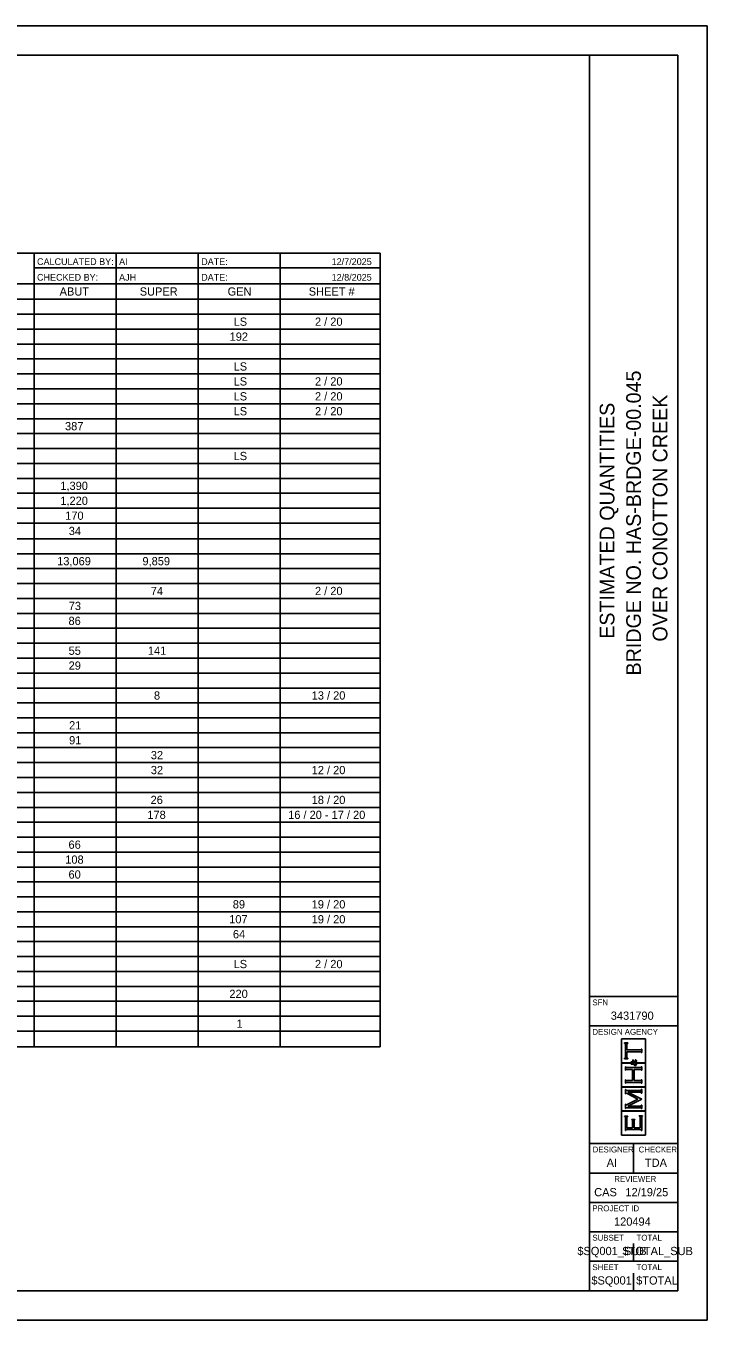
# Model space of a CAD drawing. Extents: x 0 to 34, y 0 to 22.
# Drawn here: x 22.42 to 34, y 0 to 22 of the extents above; entities that cross this region are included whole.
import ezdxf

# ---------------------------------------------------------------- set-up
doc = ezdxf.new("R2010")
doc.units = 0
for name, color, linetype in [('SH_Border', 7, 'Continuous'), ('SH_Cut_Line', 7, 'Continuous'), ('SH_Data', 7, 'Continuous'), ('SH_Text', 7, 'Continuous')]:
    doc.layers.add(name, color=color, linetype=linetype)

msp = doc.modelspace()

# ---------------------------------------------------------------- linework, layer by layer
at = {"layer": 'SH_Border'}
for p, q in [((32, 0.5), (32, 21.5)), ((32, 5.5), (33.5, 5.5)), ((32, 5), (33.5, 5)), ((32, 3), (33.5, 3)), ((32.75, 3), (32.75, 2.5)), ((32, 2.5), (33.5, 2.5)), ((32, 2), (33.5, 2)), ((32, 1.5), (33.5, 1.5)), ((32, 1), (33.5, 1))]:
    msp.add_line(p, q, dxfattribs=at)
msp.add_lwpolyline([(1.5, 21.5), (33.5, 21.5), (33.5, 0.5), (1.5, 0.5)], close=True, dxfattribs=at)
at = {"layer": 'SH_Cut_Line'}
msp.add_lwpolyline([(0, 0), (34, 0), (34, 22), (0, 22)], close=True, dxfattribs=at)
at = {"layer": 'SH_Data'}
for p, q in [((32.952, 4.779), (32.547, 4.779)), ((32.547, 4.779), (32.547, 4.375)), ((32.598, 4.704), (32.598, 4.711)), ((32.598, 4.711), (32.65, 4.711)), ((32.603, 4.703), (32.598, 4.704)), ((32.606, 4.701), (32.603, 4.703)), ((32.608, 4.699), (32.606, 4.701)), ((32.61, 4.696), (32.608, 4.699)), ((32.611, 4.692), (32.61, 4.696)), ((32.611, 4.687), (32.611, 4.692)), ((32.611, 4.468), (32.611, 4.687)), ((32.638, 4.696), (32.637, 4.692)), ((32.637, 4.692), (32.637, 4.687)), ((32.637, 4.687), (32.637, 4.593)), ((32.64, 4.699), (32.638, 4.696)), ((32.642, 4.701), (32.64, 4.699)), ((32.645, 4.703), (32.642, 4.701)), ((32.65, 4.704), (32.645, 4.703)), ((32.65, 4.711), (32.65, 4.704)), ((32.952, 4.375), (32.952, 4.779)), ((32.598, 4.45), (32.603, 4.451)), ((32.598, 4.444), (32.598, 4.45)), ((32.65, 4.444), (32.598, 4.444)), ((32.603, 4.451), (32.606, 4.453)), ((32.606, 4.453), (32.608, 4.455)), ((32.608, 4.455), (32.61, 4.458)), ((32.61, 4.458), (32.611, 4.462)), ((32.611, 4.462), (32.611, 4.468)), ((32.637, 4.593), (32.864, 4.593)), ((32.864, 4.561), (32.637, 4.561)), ((32.637, 4.561), (32.637, 4.468)), ((32.637, 4.468), (32.637, 4.462)), ((32.637, 4.462), (32.638, 4.458)), ((32.638, 4.458), (32.64, 4.455)), ((32.64, 4.455), (32.642, 4.453)), ((32.642, 4.453), (32.645, 4.451)), ((32.645, 4.451), (32.65, 4.45)), ((32.65, 4.45), (32.65, 4.444)), ((32.738, 4.393), (32.738, 4.422)), ((32.738, 4.422), (32.741, 4.422)), ((32.741, 4.422), (32.741, 4.418)), ((32.741, 4.418), (32.742, 4.415)), ((32.742, 4.415), (32.743, 4.413)), ((32.743, 4.413), (32.745, 4.411)), ((32.745, 4.411), (32.749, 4.408)), ((32.749, 4.408), (32.756, 4.404)), ((32.756, 4.404), (32.763, 4.4)), ((32.763, 4.4), (32.77, 4.396)), ((32.779, 4.423), (32.781, 4.426)), ((32.782, 4.422), (32.779, 4.423)), ((32.781, 4.426), (32.787, 4.424)), ((32.785, 4.421), (32.782, 4.422)), ((32.784, 4.398), (32.786, 4.401)), ((32.786, 4.419), (32.785, 4.421)), ((32.788, 4.417), (32.786, 4.419)), ((32.786, 4.401), (32.788, 4.404)), ((32.787, 4.424), (32.792, 4.421)), ((32.789, 4.414), (32.788, 4.417)), ((32.788, 4.404), (32.789, 4.408)), ((32.789, 4.411), (32.789, 4.414)), ((32.789, 4.408), (32.789, 4.411)), ((32.792, 4.421), (32.795, 4.418)), ((32.795, 4.418), (32.798, 4.414)), ((32.798, 4.414), (32.799, 4.41)), ((32.799, 4.401), (32.798, 4.397)), ((32.799, 4.41), (32.799, 4.405)), ((32.799, 4.405), (32.799, 4.401)), ((32.864, 4.593), (32.869, 4.593)), ((32.87, 4.561), (32.864, 4.561)), ((32.869, 4.593), (32.873, 4.594)), ((32.874, 4.56), (32.87, 4.561)), ((32.873, 4.594), (32.876, 4.596)), ((32.876, 4.559), (32.874, 4.56)), ((32.876, 4.596), (32.878, 4.597)), ((32.878, 4.557), (32.876, 4.559)), ((32.878, 4.597), (32.88, 4.601)), ((32.88, 4.553), (32.878, 4.557)), ((32.88, 4.601), (32.881, 4.606)), ((32.881, 4.548), (32.88, 4.553)), ((32.881, 4.606), (32.888, 4.606)), ((32.888, 4.548), (32.881, 4.548)), ((32.888, 4.606), (32.888, 4.548)), ((32.547, 4.375), (32.696, 4.375)), ((32.696, 4.369), (32.547, 4.369)), ((32.547, 4.369), (32.547, 3.965)), ((32.611, 4.249), (32.611, 4.307)), ((32.611, 4.307), (32.617, 4.307)), ((32.617, 4.249), (32.611, 4.249)), ((32.617, 4.307), (32.619, 4.302)), ((32.618, 4.254), (32.617, 4.249)), ((32.62, 4.258), (32.618, 4.254)), ((32.619, 4.302), (32.62, 4.298)), ((32.62, 4.298), (32.623, 4.297)), ((32.623, 4.26), (32.62, 4.258)), ((32.623, 4.297), (32.625, 4.295)), ((32.625, 4.261), (32.623, 4.26)), ((32.625, 4.295), (32.629, 4.294)), ((32.629, 4.262), (32.625, 4.261)), ((32.629, 4.294), (32.635, 4.294)), ((32.635, 4.262), (32.629, 4.262)), ((32.635, 4.294), (32.864, 4.294)), ((32.732, 4.262), (32.635, 4.262)), ((32.696, 4.375), (32.696, 4.369)), ((32.703, 4.379), (32.705, 4.383)), ((32.703, 4.373), (32.703, 4.379)), ((32.703, 4.368), (32.703, 4.373)), ((32.705, 4.363), (32.703, 4.368)), ((32.705, 4.383), (32.708, 4.387)), ((32.708, 4.358), (32.705, 4.363)), ((32.708, 4.387), (32.711, 4.39)), ((32.709, 4.379), (32.708, 4.376)), ((32.708, 4.376), (32.708, 4.373)), ((32.708, 4.373), (32.708, 4.369)), ((32.708, 4.369), (32.71, 4.366)), ((32.712, 4.353), (32.708, 4.358)), ((32.712, 4.381), (32.709, 4.379)), ((32.71, 4.366), (32.712, 4.364)), ((32.711, 4.39), (32.715, 4.392)), ((32.714, 4.383), (32.712, 4.381)), ((32.712, 4.364), (32.715, 4.362)), ((32.718, 4.35), (32.712, 4.353)), ((32.716, 4.384), (32.714, 4.383)), ((32.715, 4.392), (32.72, 4.392)), ((32.715, 4.362), (32.718, 4.361)), ((32.72, 4.384), (32.716, 4.384)), ((32.718, 4.361), (32.721, 4.361)), ((32.726, 4.35), (32.718, 4.35)), ((32.72, 4.392), (32.725, 4.392)), ((32.724, 4.384), (32.72, 4.384)), ((32.721, 4.361), (32.723, 4.361)), ((32.723, 4.361), (32.725, 4.362)), ((32.728, 4.382), (32.724, 4.384)), ((32.725, 4.392), (32.729, 4.39)), ((32.725, 4.362), (32.728, 4.362)), ((32.729, 4.35), (32.726, 4.35)), ((32.731, 4.38), (32.728, 4.382)), ((32.728, 4.362), (32.731, 4.363)), ((32.729, 4.39), (32.732, 4.387)), ((32.731, 4.35), (32.729, 4.35)), ((32.734, 4.377), (32.731, 4.38)), ((32.731, 4.363), (32.735, 4.365)), ((32.734, 4.351), (32.731, 4.35)), ((32.732, 4.387), (32.736, 4.383)), ((32.732, 4.072), (32.732, 4.262)), ((32.737, 4.372), (32.734, 4.377)), ((32.737, 4.352), (32.734, 4.351)), ((32.735, 4.365), (32.74, 4.367)), ((32.736, 4.383), (32.74, 4.378)), ((32.74, 4.367), (32.737, 4.372)), ((32.741, 4.353), (32.737, 4.352)), ((32.741, 4.393), (32.738, 4.393)), ((32.74, 4.378), (32.744, 4.369)), ((32.742, 4.396), (32.741, 4.395)), ((32.741, 4.395), (32.741, 4.393)), ((32.746, 4.355), (32.741, 4.353)), ((32.743, 4.397), (32.742, 4.396)), ((32.745, 4.399), (32.743, 4.397)), ((32.744, 4.369), (32.754, 4.375)), ((32.746, 4.399), (32.745, 4.399)), ((32.748, 4.399), (32.746, 4.399)), ((32.752, 4.344), (32.746, 4.355)), ((32.755, 4.399), (32.748, 4.399)), ((32.756, 4.36), (32.751, 4.357)), ((32.751, 4.357), (32.754, 4.352)), ((32.757, 4.337), (32.752, 4.344)), ((32.754, 4.375), (32.764, 4.381)), ((32.754, 4.352), (32.757, 4.348)), ((32.763, 4.395), (32.755, 4.399)), ((32.761, 4.363), (32.756, 4.36)), ((32.757, 4.348), (32.761, 4.345)), ((32.763, 4.333), (32.757, 4.337)), ((32.864, 4.262), (32.759, 4.262)), ((32.759, 4.262), (32.759, 4.072)), ((32.764, 4.365), (32.761, 4.363)), ((32.761, 4.345), (32.765, 4.343)), ((32.772, 4.387), (32.763, 4.395)), ((32.768, 4.329), (32.763, 4.333)), ((32.764, 4.381), (32.772, 4.387)), ((32.768, 4.367), (32.764, 4.365)), ((32.765, 4.343), (32.769, 4.341)), ((32.774, 4.372), (32.768, 4.367)), ((32.774, 4.327), (32.768, 4.329)), ((32.769, 4.341), (32.773, 4.341)), ((32.77, 4.396), (32.776, 4.391)), ((32.773, 4.341), (32.778, 4.341)), ((32.782, 4.378), (32.774, 4.372)), ((32.779, 4.327), (32.774, 4.327)), ((32.776, 4.391), (32.781, 4.395)), ((32.778, 4.341), (32.782, 4.343)), ((32.785, 4.327), (32.779, 4.327)), ((32.781, 4.395), (32.784, 4.398)), ((32.786, 4.373), (32.782, 4.378)), ((32.782, 4.343), (32.786, 4.346)), ((32.79, 4.329), (32.785, 4.327)), ((32.791, 4.386), (32.786, 4.381)), ((32.786, 4.381), (32.791, 4.376)), ((32.788, 4.369), (32.786, 4.373)), ((32.786, 4.346), (32.789, 4.349)), ((32.79, 4.367), (32.788, 4.369)), ((32.789, 4.349), (32.791, 4.353)), ((32.791, 4.364), (32.79, 4.367)), ((32.793, 4.334), (32.79, 4.329)), ((32.794, 4.39), (32.791, 4.386)), ((32.791, 4.376), (32.795, 4.37)), ((32.791, 4.361), (32.791, 4.364)), ((32.791, 4.359), (32.791, 4.361)), ((32.791, 4.353), (32.791, 4.359)), ((32.797, 4.338), (32.793, 4.334)), ((32.796, 4.394), (32.794, 4.39)), ((32.795, 4.37), (32.797, 4.366)), ((32.798, 4.397), (32.796, 4.394)), ((32.797, 4.366), (32.798, 4.361)), ((32.799, 4.344), (32.797, 4.338)), ((32.798, 4.361), (32.799, 4.357)), ((32.803, 4.369), (32.799, 4.375)), ((32.799, 4.375), (32.952, 4.375)), ((32.799, 4.357), (32.799, 4.352)), ((32.799, 4.352), (32.799, 4.344)), ((32.952, 4.369), (32.803, 4.369)), ((32.864, 4.294), (32.869, 4.294)), ((32.87, 4.262), (32.864, 4.262)), ((32.869, 4.294), (32.873, 4.295)), ((32.874, 4.261), (32.87, 4.262)), ((32.873, 4.295), (32.876, 4.297)), ((32.876, 4.26), (32.874, 4.261)), ((32.876, 4.297), (32.878, 4.298)), ((32.878, 4.258), (32.876, 4.26)), ((32.878, 4.298), (32.88, 4.302)), ((32.88, 4.254), (32.878, 4.258)), ((32.88, 4.302), (32.881, 4.307)), ((32.881, 4.249), (32.88, 4.254)), ((32.881, 4.307), (32.888, 4.307)), ((32.888, 4.249), (32.881, 4.249)), ((32.888, 4.307), (32.888, 4.249)), ((32.952, 3.965), (32.952, 4.369)), ((32.547, 3.965), (32.952, 3.965)), ((32.611, 4.027), (32.611, 4.085)), ((32.611, 4.085), (32.617, 4.085)), ((32.617, 4.027), (32.611, 4.027)), ((32.617, 4.085), (32.619, 4.08)), ((32.618, 4.032), (32.617, 4.027)), ((32.62, 4.036), (32.618, 4.032)), ((32.619, 4.08), (32.62, 4.076)), ((32.62, 4.076), (32.623, 4.074)), ((32.623, 4.037), (32.62, 4.036)), ((32.623, 4.074), (32.625, 4.073)), ((32.625, 4.039), (32.623, 4.037)), ((32.625, 4.073), (32.629, 4.072)), ((32.629, 4.04), (32.625, 4.039)), ((32.629, 4.072), (32.635, 4.072)), ((32.635, 4.04), (32.629, 4.04)), ((32.635, 4.072), (32.732, 4.072)), ((32.864, 4.04), (32.635, 4.04)), ((32.75, 4), (32.75, 4)), ((32.759, 4.072), (32.864, 4.072)), ((32.864, 4.072), (32.87, 4.072)), ((32.87, 4.04), (32.864, 4.04)), ((32.87, 4.072), (32.874, 4.073)), ((32.874, 4.039), (32.87, 4.04)), ((32.874, 4.073), (32.876, 4.074)), ((32.876, 4.038), (32.874, 4.039)), ((32.876, 4.074), (32.878, 4.076)), ((32.878, 4.036), (32.876, 4.038)), ((32.878, 4.076), (32.88, 4.08)), ((32.88, 4.032), (32.878, 4.036)), ((32.88, 4.08), (32.881, 4.085)), ((32.881, 4.027), (32.88, 4.032)), ((32.881, 4.085), (32.888, 4.085)), ((32.888, 4.027), (32.881, 4.027)), ((32.888, 4.085), (32.888, 4.027)), ((32.952, 3.959), (32.547, 3.959)), ((32.547, 3.959), (32.547, 3.555)), ((32.611, 3.845), (32.611, 3.918)), ((32.611, 3.918), (32.617, 3.918)), ((32.617, 3.845), (32.611, 3.845)), ((32.617, 3.918), (32.619, 3.912)), ((32.62, 3.852), (32.617, 3.845)), ((32.619, 3.912), (32.62, 3.909)), ((32.62, 3.909), (32.623, 3.907)), ((32.622, 3.855), (32.62, 3.852)), ((32.626, 3.855), (32.622, 3.855)), ((32.623, 3.907), (32.625, 3.905)), ((32.625, 3.905), (32.629, 3.905)), ((32.629, 3.855), (32.626, 3.855)), ((32.629, 3.905), (32.635, 3.905)), ((32.633, 3.853), (32.629, 3.855)), ((32.64, 3.85), (32.633, 3.853)), ((32.635, 3.905), (32.864, 3.905)), ((32.825, 3.757), (32.64, 3.85)), ((32.641, 3.665), (32.825, 3.757)), ((32.864, 3.873), (32.654, 3.873)), ((32.654, 3.873), (32.888, 3.755)), ((32.888, 3.755), (32.654, 3.638)), ((32.864, 3.905), (32.869, 3.905)), ((32.87, 3.873), (32.864, 3.873)), ((32.869, 3.905), (32.873, 3.905)), ((32.874, 3.872), (32.87, 3.873)), ((32.873, 3.905), (32.876, 3.907)), ((32.876, 3.87), (32.874, 3.872)), ((32.876, 3.907), (32.878, 3.909)), ((32.878, 3.869), (32.876, 3.87)), ((32.878, 3.909), (32.88, 3.912)), ((32.88, 3.865), (32.878, 3.869)), ((32.88, 3.912), (32.881, 3.918)), ((32.881, 3.86), (32.88, 3.865)), ((32.881, 3.918), (32.888, 3.918)), ((32.888, 3.86), (32.881, 3.86)), ((32.888, 3.918), (32.888, 3.86)), ((32.952, 3.555), (32.952, 3.959)), ((32.547, 3.555), (32.952, 3.555)), ((32.952, 3.549), (32.547, 3.549)), ((32.547, 3.549), (32.547, 3.145)), ((32.611, 3.596), (32.611, 3.668)), ((32.611, 3.668), (32.617, 3.668)), ((32.617, 3.596), (32.611, 3.596)), ((32.617, 3.668), (32.62, 3.662)), ((32.618, 3.602), (32.617, 3.596)), ((32.62, 3.605), (32.618, 3.602)), ((32.62, 3.662), (32.622, 3.658)), ((32.623, 3.607), (32.62, 3.605)), ((32.622, 3.658), (32.626, 3.658)), ((32.625, 3.609), (32.623, 3.607)), ((32.629, 3.609), (32.625, 3.609)), ((32.626, 3.658), (32.627, 3.658)), ((32.627, 3.658), (32.633, 3.661)), ((32.635, 3.609), (32.629, 3.609)), ((32.633, 3.661), (32.641, 3.665)), ((32.864, 3.609), (32.635, 3.609)), ((32.654, 3.638), (32.864, 3.638)), ((32.864, 3.638), (32.869, 3.638)), ((32.87, 3.609), (32.864, 3.609)), ((32.869, 3.638), (32.873, 3.639)), ((32.874, 3.609), (32.87, 3.609)), ((32.873, 3.639), (32.876, 3.641)), ((32.876, 3.607), (32.874, 3.609)), ((32.876, 3.641), (32.878, 3.643)), ((32.878, 3.605), (32.876, 3.607)), ((32.878, 3.643), (32.88, 3.646)), ((32.88, 3.602), (32.878, 3.605)), ((32.88, 3.646), (32.881, 3.651)), ((32.881, 3.596), (32.88, 3.602)), ((32.881, 3.651), (32.888, 3.651)), ((32.888, 3.596), (32.881, 3.596)), ((32.888, 3.651), (32.888, 3.596)), ((32.952, 3.145), (32.952, 3.549)), ((32.598, 3.462), (32.598, 3.469)), ((32.598, 3.469), (32.65, 3.469)), ((32.603, 3.461), (32.598, 3.462)), ((32.606, 3.459), (32.603, 3.461)), ((32.608, 3.457), (32.606, 3.459)), ((32.61, 3.455), (32.608, 3.457)), ((32.611, 3.451), (32.61, 3.455)), ((32.611, 3.445), (32.611, 3.451)), ((32.611, 3.225), (32.611, 3.445)), ((32.64, 3.457), (32.638, 3.455)), ((32.638, 3.455), (32.638, 3.451)), ((32.638, 3.451), (32.638, 3.445)), ((32.638, 3.445), (32.638, 3.27)), ((32.642, 3.459), (32.64, 3.457)), ((32.645, 3.461), (32.642, 3.459)), ((32.65, 3.462), (32.645, 3.461)), ((32.65, 3.469), (32.65, 3.462)), ((32.719, 3.402), (32.719, 3.408)), ((32.719, 3.408), (32.772, 3.408)), ((32.724, 3.401), (32.719, 3.402)), ((32.728, 3.399), (32.724, 3.401)), ((32.729, 3.396), (32.728, 3.399)), ((32.731, 3.394), (32.729, 3.396)), ((32.732, 3.39), (32.731, 3.394)), ((32.732, 3.384), (32.732, 3.39)), ((32.732, 3.27), (32.732, 3.384)), ((32.76, 3.394), (32.759, 3.39)), ((32.759, 3.39), (32.759, 3.384)), ((32.759, 3.384), (32.759, 3.27)), ((32.761, 3.396), (32.76, 3.394)), ((32.763, 3.399), (32.761, 3.396)), ((32.767, 3.401), (32.763, 3.399)), ((32.772, 3.402), (32.767, 3.401)), ((32.772, 3.408), (32.772, 3.402)), ((32.848, 3.465), (32.848, 3.472)), ((32.848, 3.472), (32.901, 3.472)), ((32.853, 3.464), (32.848, 3.465)), ((32.857, 3.462), (32.853, 3.464)), ((32.859, 3.46), (32.857, 3.462)), ((32.86, 3.458), (32.859, 3.46)), ((32.861, 3.453), (32.86, 3.458)), ((32.861, 3.448), (32.861, 3.453)), ((32.861, 3.27), (32.861, 3.448)), ((32.889, 3.457), (32.888, 3.453)), ((32.888, 3.453), (32.888, 3.448)), ((32.888, 3.448), (32.888, 3.225)), ((32.891, 3.46), (32.889, 3.457)), ((32.892, 3.462), (32.891, 3.46)), ((32.896, 3.464), (32.892, 3.462)), ((32.901, 3.465), (32.896, 3.464)), ((32.901, 3.472), (32.901, 3.465)), ((32.547, 3.145), (32.952, 3.145)), ((32.617, 3.225), (32.611, 3.225)), ((32.619, 3.23), (32.617, 3.225)), ((32.62, 3.234), (32.619, 3.23)), ((32.623, 3.235), (32.62, 3.234)), ((32.625, 3.237), (32.623, 3.235)), ((32.629, 3.238), (32.625, 3.237)), ((32.635, 3.238), (32.629, 3.238)), ((32.864, 3.238), (32.635, 3.238)), ((32.638, 3.27), (32.732, 3.27)), ((32.759, 3.27), (32.861, 3.27)), ((32.87, 3.238), (32.864, 3.238)), ((32.874, 3.237), (32.87, 3.238)), ((32.876, 3.235), (32.874, 3.237)), ((32.878, 3.234), (32.876, 3.235)), ((32.88, 3.23), (32.878, 3.234)), ((32.881, 3.225), (32.88, 3.23)), ((32.888, 3.225), (32.881, 3.225)), ((32.75, 1), (32.75, 1.3)), ((32.375, 0.675), (32.375, 0.675)), ((32.75, 0.5), (32.75, 0.8))]:
    msp.add_line(p, q, dxfattribs=at)
at = {"layer": 'SH_Text'}
for p, q in [((3.996, 18.138), (28.445, 18.138)), ((22.561, 18.138), (22.561, 4.646)), ((23.956, 18.138), (23.956, 4.646)), ((25.351, 18.138), (25.351, 4.646)), ((26.746, 18.138), (26.746, 4.646)), ((28.445, 18.138), (28.445, 4.646)), ((22.561, 17.885), (28.445, 17.885)), ((3.996, 17.618), (28.445, 17.618)), ((3.996, 17.352), (28.445, 17.352)), ((3.996, 17.098), (28.445, 17.098)), ((3.996, 16.845), (28.445, 16.845)), ((3.996, 16.591), (28.445, 16.591)), ((3.996, 16.338), (28.445, 16.338)), ((3.996, 16.084), (28.445, 16.084)), ((3.996, 15.83), (28.445, 15.83)), ((3.996, 15.577), (28.445, 15.577)), ((3.996, 15.323), (28.445, 15.323)), ((3.996, 15.069), (28.445, 15.069)), ((3.996, 14.816), (28.445, 14.816)), ((3.996, 14.562), (28.445, 14.562)), ((3.996, 14.309), (28.445, 14.309)), ((3.996, 14.055), (28.445, 14.055)), ((3.996, 13.801), (28.445, 13.801)), ((3.996, 13.548), (28.445, 13.548)), ((3.996, 13.281), (28.445, 13.281)), ((3.996, 13.028), (28.445, 13.028)), ((3.996, 12.774), (28.445, 12.774)), ((3.996, 12.521), (28.445, 12.521)), ((3.996, 12.267), (28.445, 12.267)), ((3.996, 12.013), (28.445, 12.013)), ((3.996, 11.76), (28.445, 11.76)), ((3.996, 11.506), (28.445, 11.506)), ((3.996, 11.252), (28.445, 11.252)), ((3.996, 10.999), (28.445, 10.999)), ((3.996, 10.745), (28.445, 10.745)), ((3.996, 10.492), (28.445, 10.492)), ((3.996, 10.238), (28.445, 10.238)), ((3.996, 9.984), (28.445, 9.984)), ((3.996, 9.731), (28.445, 9.731)), ((3.996, 9.477), (28.445, 9.477)), ((3.996, 9.223), (28.445, 9.223)), ((3.996, 8.97), (28.445, 8.97)), ((3.996, 8.716), (28.445, 8.716)), ((3.996, 8.463), (28.445, 8.463)), ((3.996, 8.209), (28.445, 8.209)), ((3.996, 7.955), (28.445, 7.955)), ((3.996, 7.702), (28.445, 7.702)), ((3.996, 7.448), (28.445, 7.448)), ((3.996, 7.194), (28.445, 7.194)), ((3.996, 6.941), (28.445, 6.941)), ((3.996, 6.687), (28.445, 6.687)), ((3.996, 6.434), (28.445, 6.434)), ((3.996, 6.18), (28.445, 6.18)), ((3.996, 5.926), (28.445, 5.926)), ((3.996, 5.673), (28.445, 5.673)), ((3.996, 5.419), (28.445, 5.419)), ((3.996, 5.165), (28.445, 5.165)), ((3.996, 4.912), (28.445, 4.912)), ((3.996, 4.646), (28.445, 4.646))]:
    msp.add_line(p, q, dxfattribs=at)

# ---------------------------------------------------------------- texts
at = {"layer": 'SH_Data'}
for s, p in [('BRIDGE NO. HAS-BRDGE-00.045', (32.875, 10.958)), ('OVER CONOTTON CREEK', (33.325, 11.534)), ('ESTIMATED QUANTITIES', (32.425, 11.582))]:
    msp.add_text(s, height=0.25, rotation=90, dxfattribs=at).set_placement(p)
for s, height, p in [('SFN', 0.1, (32.05, 5.35)), ('3431790', 0.14, (32.363, 5.105)), ('DESIGN AGENCY', 0.1, (32.05, 4.85)), ('DESIGNER', 0.1, (32.054, 2.85)), ('CHECKER', 0.1, (32.835, 2.85)), ('AI', 0.14, (32.293, 2.605)), ('TDA', 0.14, (32.943, 2.605)), ('REVIEWER', 0.1, (32.422, 2.35)), ('CAS', 0.14, (32.081, 2.105)), ('12/19/25', 0.14, (32.611, 2.105)), ('PROJECT ID', 0.1, (32.05, 1.85)), ('120494', 0.14, (32.418, 1.605)), ('SUBSET', 0.1, (32.05, 1.35)), ('TOTAL', 0.1, (32.8, 1.35)), ('$SQ001_SUB', 0.14, (31.795, 1.105)), ('$TOTAL_SUB', 0.14, (32.562, 1.105)), ('SHEET', 0.1, (32.05, 0.85)), ('TOTAL', 0.1, (32.8, 0.85)), ('$SQ001', 0.14, (32.033, 0.605)), ('$TOTAL', 0.14, (32.794, 0.605))]:
    msp.add_text(s, height=height, dxfattribs=at).set_placement(p)
at = {"layer": 'SH_Text'}
for s, height, p in [('CALCULATED BY:', 0.11455, (22.612, 17.935)), ('AI', 0.1145, (24.007, 17.935)), ('DATE:', 0.1145, (25.402, 17.935)), ('12/7/2025', 0.1145, (27.619, 17.935)), ('CHECKED BY:', 0.11455, (22.612, 17.669)), ('AJH', 0.1145, (24.007, 17.669)), ('DATE:', 0.1145, (25.402, 17.669)), ('12/8/2025', 0.1145, (27.619, 17.669)), ('ABUT', 0.14, (22.996, 17.415)), ('SUPER', 0.14, (24.357, 17.415)), ('GEN', 0.14, (25.851, 17.415)), ('SHEET #', 0.14, (27.229, 17.415)), ('LS', 0.14, (25.953, 16.902)), ('2 / 20', 0.14, (27.336, 16.902)), ('192', 0.14, (25.885, 16.648)), ('LS', 0.14, (25.953, 16.141)), ('LS', 0.14, (25.953, 15.887)), ('2 / 20', 0.14, (27.336, 15.887)), ('LS', 0.14, (25.953, 15.633)), ('2 / 20', 0.14, (27.336, 15.633)), ('LS', 0.14, (25.953, 15.38)), ('2 / 20', 0.14, (27.336, 15.38)), ('387', 0.14, (23.088, 15.126)), ('LS', 0.14, (25.953, 14.619)), ('1,390', 0.14, (23.008, 14.112)), ('1,220', 0.14, (23.008, 13.858)), ('170', 0.14, (23.091, 13.604)), ('34', 0.14, (23.151, 13.345)), ('13,069', 0.14, (22.954, 12.831)), ('9,859', 0.14, (24.404, 12.831)), ('74', 0.14, (24.546, 12.324)), ('2 / 20', 0.14, (27.336, 12.324)), ('73', 0.14, (23.151, 12.07)), ('86', 0.14, (23.147, 11.816)), ('55', 0.14, (23.149, 11.309)), ('141', 0.14, (24.496, 11.309)), ('29', 0.14, (23.149, 11.056)), ('8', 0.14, (24.599, 10.548)), ('13 / 20', 0.14, (27.28, 10.548)), ('21', 0.14, (23.157, 10.041)), ('91', 0.14, (23.157, 9.787)), ('32', 0.14, (24.546, 9.534)), ('32', 0.14, (24.546, 9.28)), ('12 / 20', 0.14, (27.28, 9.28)), ('26', 0.14, (24.542, 8.773)), ('18 / 20', 0.14, (27.28, 8.773)), ('178', 0.14, (24.487, 8.519)), ('16 / 20 - 17 / 20', 0.14, (26.88, 8.519)), ('66', 0.14, (23.147, 8.012)), ('108', 0.14, (23.092, 7.758)), ('60', 0.14, (23.147, 7.505)), ('89', 0.14, (25.939, 6.998)), ('19 / 20', 0.14, (27.28, 6.998)), ('107', 0.14, (25.878, 6.744)), ('19 / 20', 0.14, (27.28, 6.744)), ('64', 0.14, (25.941, 6.49)), ('LS', 0.14, (25.953, 5.983)), ('2 / 20', 0.14, (27.336, 5.983)), ('220', 0.14, (25.881, 5.476)), ('1', 0.14, (26.003, 4.969))]:
    msp.add_text(s, height=height, dxfattribs=at).set_placement(p)

doc.saveas('drawing.dxf')
